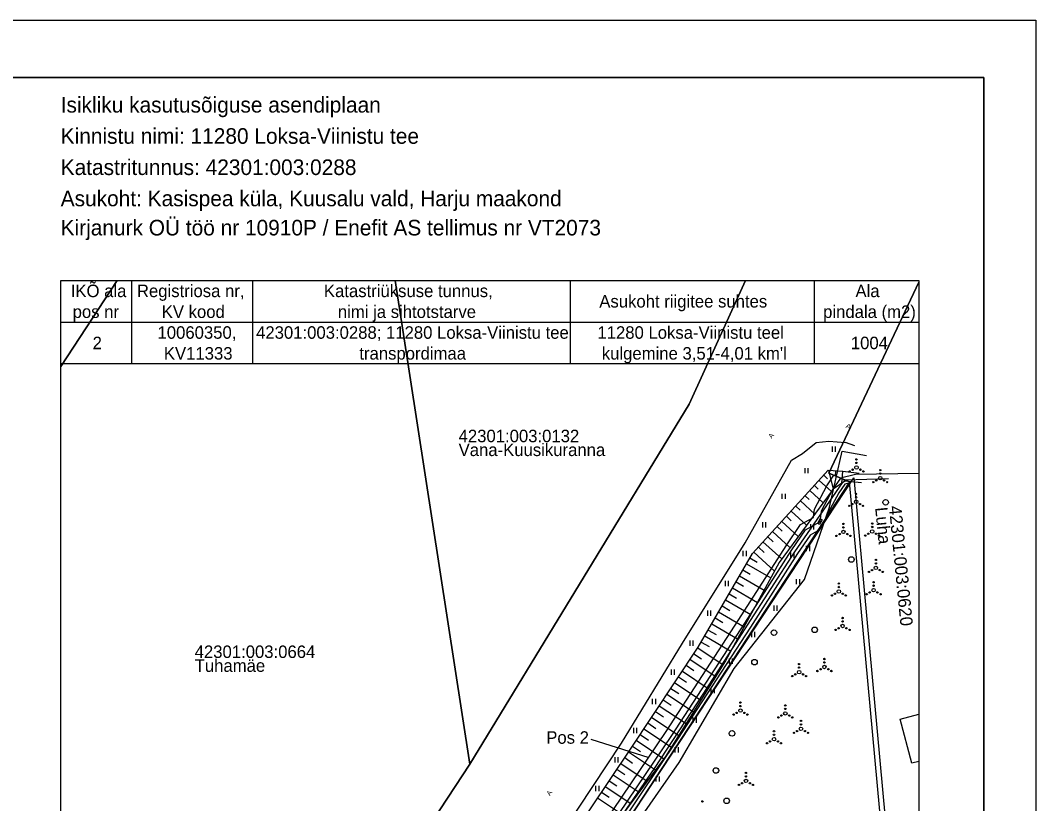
# Model space of a CAD drawing. Extents: x 599446 to 599962, y 6608194 to 6608886.
# Drawn here: x 599815.8 to 599962.3, y 6608773.2 to 6608886.1 of the extents above; entities that cross this region are included whole.
import ezdxf

# ---------------------------------------------------------------- set-up
doc = ezdxf.new("R2010")
doc.units = 0
for name, color, linetype in [('Default', 7, 'Continuous'), ('HALJASTUS', 7, 'Continuous'), ('HOONE', 7, 'Continuous'), ('KASUTUSALA', 7, 'Continuous'), ('MPKAABEL', 7, 'Continuous'), ('PIIR', 7, 'Continuous'), ('PR_SIDE', 7, 'Continuous'), ('proj_trass_kliendiliin kaabel', 7, 'Continuous'), ('RELJEEF', 7, 'Continuous'), ('TEE', 7, 'Continuous'), ('VORMISTUS_3', 7, 'Continuous')]:
    doc.layers.add(name, color=color, linetype=linetype)

msp = doc.modelspace()

# ---------------------------------------------------------------- linework, layer by layer
at = {"layer": 'Default'}
msp.add_lwpolyline([(599930.83, 6608813.56), (599931.21, 6608814.28), (599931.48, 6608814.13), (599931.1, 6608813.42)], close=True, dxfattribs=at)
at = {"layer": 'HALJASTUS'}
for p, q in [((599932.9, 6608824.67), (599932.9, 6608823.91)), ((599933.35, 6608824.67), (599933.35, 6608823.91)), ((599928.97, 6608821.58), (599928.97, 6608820.82)), ((599929.42, 6608821.58), (599929.42, 6608820.82)), ((599925.68, 6608817.88), (599925.68, 6608817.12)), ((599926.14, 6608817.88), (599926.14, 6608817.12)), ((599922.86, 6608813.76), (599922.86, 6608812.99)), ((599923.31, 6608813.76), (599923.31, 6608812.99)), ((599929.78, 6608813.48), (599929.78, 6608812.72)), ((599930.24, 6608813.48), (599930.24, 6608812.72)), ((599920.05, 6608809.62), (599920.05, 6608808.86)), ((599920.5, 6608809.62), (599920.5, 6608808.86)), ((599926.91, 6608809.38), (599926.91, 6608808.62)), ((599927.37, 6608809.38), (599927.37, 6608808.62)), ((599929.19, 6608810.35), (599929.19, 6608809.59)), ((599929.64, 6608810.35), (599929.64, 6608809.59)), ((599917.49, 6608805.33), (599917.49, 6608804.56)), ((599917.94, 6608805.33), (599917.94, 6608804.56)), ((599927.74, 6608805.58), (599927.74, 6608804.82)), ((599928.19, 6608805.58), (599928.19, 6608804.82)), ((599914.93, 6608801.03), (599914.93, 6608800.27)), ((599915.39, 6608801.03), (599915.39, 6608800.27)), ((599924.5, 6608801.77), (599924.5, 6608801.01)), ((599924.96, 6608801.77), (599924.96, 6608801.01)), ((599921.27, 6608797.95), (599921.27, 6608797.19)), ((599921.73, 6608797.95), (599921.73, 6608797.19)), ((599912.38, 6608796.73), (599912.38, 6608795.97)), ((599912.83, 6608796.73), (599912.83, 6608795.97)), ((599918.04, 6608794.14), (599918.04, 6608793.37)), ((599918.5, 6608794.14), (599918.5, 6608793.37)), ((599909.68, 6608792.52), (599909.68, 6608791.76)), ((599910.13, 6608792.52), (599910.13, 6608791.76)), ((599915.43, 6608789.87), (599915.43, 6608789.11)), ((599915.89, 6608789.87), (599915.89, 6608789.11)), ((599906.97, 6608788.32), (599906.97, 6608787.56)), ((599907.43, 6608788.32), (599907.43, 6608787.56)), ((599912.83, 6608785.6), (599912.83, 6608784.84)), ((599913.29, 6608785.6), (599913.29, 6608784.84)), ((599904.27, 6608784.11), (599904.27, 6608783.35)), ((599904.72, 6608784.11), (599904.72, 6608783.35)), ((599901.56, 6608779.91), (599901.56, 6608779.15)), ((599902.02, 6608779.91), (599902.02, 6608779.15)), ((599910.23, 6608781.33), (599910.23, 6608780.57)), ((599910.69, 6608781.33), (599910.69, 6608780.57)), ((599907.5, 6608777.14), (599907.5, 6608776.38)), ((599907.96, 6608777.14), (599907.96, 6608776.38)), ((599898.79, 6608775.75), (599898.79, 6608774.99)), ((599899.24, 6608775.75), (599899.24, 6608774.99))]:
    msp.add_line(p, q, dxfattribs=at)
msp.add_lwpolyline([(599852.54, 6608691.11), (599853.6, 6608692.39), (599867.47, 6608716.75), (599880.24, 6608735.62), (599894.9, 6608756.22), (599910.84, 6608779.13), (599918.77, 6608792.66), (599928.93, 6608805.49), (599932.52, 6608815.94), (599934.35, 6608823.99), (599937.89, 6608823.39)], dxfattribs=at)
for centre, radius in [((599936.42, 6608822.81), 0.1), ((599936.42, 6608822.31), 0.1), ((599935.42, 6608821.09), 0.1), ((599935.86, 6608821.34), 0.1), ((599936.42, 6608821.66), 0.25), ((599936.99, 6608821.34), 0.1), ((599937.42, 6608821.09), 0.1), ((599939.85, 6608821.27), 0.1), ((599938.85, 6608819.54), 0.1), ((599939.28, 6608819.79), 0.1), ((599939.85, 6608820.12), 0.25), ((599939.85, 6608820.77), 0.1), ((599940.41, 6608819.79), 0.1), ((599940.85, 6608819.54), 0.1), ((599936.38, 6608816.71), 0.25), ((599936.38, 6608817.86), 0.1), ((599936.38, 6608817.36), 0.1), ((599940.63, 6608816.63), 0.4), ((599935.38, 6608816.13), 0.1), ((599935.81, 6608816.38), 0.1), ((599936.94, 6608816.38), 0.1), ((599937.38, 6608816.13), 0.1), ((599934.54, 6608813.52), 0.1), ((599938.69, 6608813.58), 0.1), ((599933.98, 6608812.05), 0.1), ((599934.54, 6608812.37), 0.25), ((599934.54, 6608813.02), 0.1), ((599935.11, 6608812.05), 0.1), ((599938.12, 6608812.1), 0.1), ((599938.69, 6608812.43), 0.25), ((599938.69, 6608813.08), 0.1), ((599939.25, 6608812.1), 0.1), ((599933.54, 6608811.8), 0.1), ((599935.54, 6608811.8), 0.1), ((599937.69, 6608811.85), 0.1), ((599939.69, 6608811.85), 0.1), ((599935.69, 6608808.39), 0.4), ((599939.22, 6608808.33), 0.1), ((599939.22, 6608807.83), 0.1), ((599938.22, 6608806.61), 0.1), ((599938.66, 6608806.86), 0.1), ((599939.22, 6608807.18), 0.25), ((599939.79, 6608806.86), 0.1), ((599940.22, 6608806.61), 0.1), ((599933.88, 6608804.93), 0.1), ((599938.89, 6608805.12), 0.1), ((599933.32, 6608803.46), 0.1), ((599933.88, 6608803.78), 0.25), ((599933.88, 6608804.43), 0.1), ((599934.45, 6608803.46), 0.1), ((599937.89, 6608803.39), 0.1), ((599938.32, 6608803.64), 0.1), ((599938.89, 6608803.97), 0.25), ((599938.89, 6608804.62), 0.1), ((599939.45, 6608803.64), 0.1), ((599939.89, 6608803.39), 0.1), ((599932.88, 6608803.21), 0.1), ((599934.88, 6608803.21), 0.1), ((599934.42, 6608798.81), 0.25), ((599934.42, 6608799.96), 0.1), ((599934.42, 6608799.46), 0.1), ((599924.52, 6608797.85), 0.4), ((599930.39, 6608798.25), 0.4), ((599933.42, 6608798.24), 0.1), ((599933.85, 6608798.49), 0.1), ((599934.98, 6608798.49), 0.1), ((599935.42, 6608798.24), 0.1), ((599921.71, 6608793.6), 0.4), ((599928.15, 6608793.31), 0.1), ((599931.8, 6608792.9), 0.25), ((599931.8, 6608794.05), 0.1), ((599931.8, 6608793.55), 0.1), ((599927.15, 6608791.59), 0.1), ((599927.59, 6608791.84), 0.1), ((599928.15, 6608792.16), 0.25), ((599928.15, 6608792.81), 0.1), ((599928.72, 6608791.84), 0.1), ((599929.15, 6608791.59), 0.1), ((599930.8, 6608792.32), 0.1), ((599931.24, 6608792.57), 0.1), ((599932.37, 6608792.57), 0.1), ((599932.8, 6608792.32), 0.1), ((599919.69, 6608787.77), 0.1), ((599919.69, 6608787.27), 0.1), ((599926.16, 6608787.36), 0.1), ((599918.69, 6608786.04), 0.1), ((599919.13, 6608786.29), 0.1), ((599919.69, 6608786.62), 0.25), ((599920.26, 6608786.29), 0.1), ((599920.69, 6608786.04), 0.1), ((599925.59, 6608785.89), 0.1), ((599926.16, 6608786.21), 0.25), ((599926.16, 6608786.86), 0.1), ((599926.72, 6608785.89), 0.1), ((599925.16, 6608785.64), 0.1), ((599927.16, 6608785.64), 0.1), ((599928.42, 6608785.13), 0.1), ((599928.42, 6608784.63), 0.1), ((599918.48, 6608783.33), 0.4), ((599924.53, 6608783.64), 0.1), ((599924.53, 6608783.14), 0.1), ((599927.42, 6608783.41), 0.1), ((599927.86, 6608783.66), 0.1), ((599928.42, 6608783.98), 0.25), ((599928.99, 6608783.66), 0.1), ((599929.42, 6608783.41), 0.1), ((599923.53, 6608781.92), 0.1), ((599923.96, 6608782.17), 0.1), ((599924.53, 6608782.49), 0.25), ((599925.09, 6608782.17), 0.1), ((599925.53, 6608781.92), 0.1), ((599916.15, 6608777.98), 0.4), ((599920.48, 6608777.63), 0.1), ((599920.48, 6608777.13), 0.1), ((599919.48, 6608775.9), 0.1), ((599919.92, 6608776.15), 0.1), ((599920.48, 6608776.48), 0.25), ((599921.05, 6608776.15), 0.1), ((599921.48, 6608775.9), 0.1), ((599914.21, 6608773.52), 0.1), ((599917.69, 6608773.61), 0.4)]:
    msp.add_circle(centre, radius, dxfattribs=at)
at = {"layer": 'HOONE'}
msp.add_lwpolyline([(599945.4, 6608779.28), (599944.41, 6608779.02), (599942.72, 6608785.37), (599945.4, 6608786.08)], dxfattribs=at)
at = {"layer": 'KASUTUSALA'}
msp.add_lwpolyline([(599897.59, 6608766.72), (599908.96, 6608783.58), (599919.46, 6608799.75), (599926.27, 6608810.34), (599928.36, 6608813.42), (599930.22, 6608814.47), (599930.37, 6608815.67), (599932.17, 6608819.03), (599933.17, 6608820.53), (599935.43, 6608819.59), (599935.3, 6608819.39), (599934.73, 6608819.25), (599933.89, 6608818), (599932.31, 6608815.06), (599932.27, 6608814.78), (599930.76, 6608812.48), (599929.75, 6608811.91), (599927.94, 6608809.24), (599921.14, 6608798.66), (599910.63, 6608782.48), (599899.24, 6608765.59)], dxfattribs=at)
at = {"layer": 'MPKAABEL'}
msp.add_lwpolyline([(599850.04, 6608691.11), (599852.92, 6608695.67), (599859.86, 6608706.62), (599864.89, 6608714.39), (599871.03, 6608723.6), (599876.62, 6608731.9), (599883.44, 6608742.77), (599889.53, 6608752.39), (599895.65, 6608761.17), (599900.8, 6608768.87), (599907.3, 6608778.25), (599914.42, 6608789.11), (599920.72, 6608798.93), (599927.52, 6608809.51), (599934.42, 6608819.43), (599934.81, 6608819.9), (599941.02, 6608820.09)], dxfattribs=at)
at = {"layer": 'PIIR'}
for points in [[(599829.8, 6608848.61), (599821.65, 6608836.23)], [(599821.65, 6608836.23), (599829.8, 6608848.61)], [(599869.91, 6608848.61), (599880.68, 6608778.91), (599822.96, 6608691.11)], [(599822.96, 6608691.11), (599880.68, 6608778.91), (599912.29, 6608830.77), (599920.4, 6608848.61)], [(599945.4, 6608848.37), (599932.44, 6608820.83), (599935.43, 6608819.59), (599886.06, 6608744.32), (599851.22, 6608691.11)], [(599920.4, 6608848.61), (599912.29, 6608830.77), (599880.68, 6608778.91), (599869.91, 6608848.61)], [(599945.4, 6608711.12), (599935.43, 6608819.59), (599932.44, 6608820.83), (599945.4, 6608848.39)], [(599894.31, 6608691.11), (599886.06, 6608744.32), (599936.05, 6608820.15), (599945.4, 6608718.31)]]:
    msp.add_lwpolyline(points, dxfattribs=at)
at = {"layer": 'PR_SIDE'}
msp.add_lwpolyline([(599780.53, 6608585.3), (599792.21, 6608602.29), (599793.2, 6608606.88), (599806.34, 6608627.01), (599816.97, 6608642.78), (599827.08, 6608657.37), (599832.75, 6608665.24), (599837.96, 6608672.78), (599843.96, 6608682.55), (599849.32, 6608690.88), (599859.61, 6608707.16), (599866.76, 6608718.14), (599874.33, 6608729.39), (599883.02, 6608743.03), (599889.12, 6608752.66), (599898.41, 6608766.16), (599909.8, 6608783.03), (599920.3, 6608799.2), (599927.11, 6608809.79), (599929.06, 6608812.66), (599931.15, 6608813.84)], dxfattribs=at)
at = {"layer": 'proj_trass_kliendiliin kaabel'}
msp.add_lwpolyline([(599945.4, 6608820.77), (599936.29, 6608820.65), (599934.12, 6608820.14), (599933.03, 6608818.51), (599931.34, 6608815.37), (599931.15, 6608813.84)], dxfattribs=at)
at = {"layer": 'RELJEEF'}
for p, q in [((599932.39, 6608821.25), (599933.04, 6608818.51)), ((599933.39, 6608821.18), (599933.34, 6608820.42)), ((599934.39, 6608821.12), (599934.28, 6608819.35)), ((599931.03, 6608819.8), (599932.8, 6608818.18)), ((599931.71, 6608820.53), (599932.26, 6608820.03)), ((599929.68, 6608818.32), (599931.61, 6608816.56)), ((599930.36, 6608819.06), (599930.91, 6608818.55)), ((599928.34, 6608816.84), (599930.41, 6608814.94)), ((599929.01, 6608817.58), (599929.61, 6608817.03)), ((599926.99, 6608815.36), (599929.22, 6608813.33)), ((599927.66, 6608816.1), (599928.31, 6608815.51)), ((599925.64, 6608813.89), (599928.03, 6608811.71)), ((599926.31, 6608814.62), (599927.01, 6608813.99)), ((599924.29, 6608812.41), (599926.84, 6608810.09)), ((599924.97, 6608813.15), (599925.71, 6608812.47)), ((599922.94, 6608810.93), (599925.65, 6608808.47)), ((599923.62, 6608811.67), (599924.41, 6608810.95)), ((599921.6, 6608809.45), (599924.6, 6608806.71)), ((599922.27, 6608810.19), (599923.12, 6608809.42)), ((599920.55, 6608807.76), (599924.06, 6608805.73)), ((599921.05, 6608808.62), (599922.1, 6608808.02)), ((599920.05, 6608806.89), (599921.11, 6608806.28)), ((599919.05, 6608805.16), (599920.12, 6608804.54)), ((599919.55, 6608806.03), (599923.1, 6608803.97)), ((599918.05, 6608803.43), (599919.13, 6608802.8)), ((599918.55, 6608804.29), (599922.14, 6608802.21)), ((599917.54, 6608802.56), (599921.19, 6608800.46)), ((599916.54, 6608800.83), (599920.23, 6608798.7)), ((599917.04, 6608801.7), (599918.14, 6608801.06)), ((599915.54, 6608799.1), (599919.27, 6608796.94)), ((599916.04, 6608799.97), (599917.15, 6608799.32)), ((599915.04, 6608798.23), (599916.17, 6608797.58)), ((599914.04, 6608796.5), (599915.18, 6608795.85)), ((599914.54, 6608797.37), (599918.31, 6608795.19)), ((599912.98, 6608794.81), (599914.08, 6608794.07)), ((599913.53, 6608795.64), (599917.18, 6608793.21)), ((599911.87, 6608793.15), (599912.98, 6608792.4)), ((599912.42, 6608793.98), (599916.12, 6608791.51)), ((599911.31, 6608792.31), (599915.05, 6608789.82)), ((599910.2, 6608790.65), (599913.99, 6608788.12)), ((599910.76, 6608791.48), (599911.89, 6608790.73)), ((599909.09, 6608788.99), (599912.93, 6608786.43)), ((599909.65, 6608789.82), (599910.79, 6608789.06)), ((599907.98, 6608787.32), (599911.86, 6608784.74)), ((599908.54, 6608788.15), (599909.69, 6608787.38)), ((599907.43, 6608786.49), (599908.6, 6608785.71)), ((599906.32, 6608784.83), (599907.5, 6608784.04)), ((599906.87, 6608785.66), (599910.8, 6608783.04)), ((599905.21, 6608783.16), (599906.41, 6608782.36)), ((599905.76, 6608784), (599909.73, 6608781.35)), ((599904.1, 6608781.5), (599905.28, 6608780.71)), ((599904.65, 6608782.33), (599908.64, 6608779.67)), ((599903.54, 6608780.67), (599907.44, 6608778.06)), ((599902.43, 6608779.01), (599906.25, 6608776.45)), ((599902.99, 6608779.84), (599904.14, 6608779.06)), ((599901.32, 6608777.34), (599905.06, 6608774.84)), ((599901.87, 6608778.18), (599903.01, 6608777.42)), ((599900.2, 6608775.68), (599903.87, 6608773.23)), ((599900.76, 6608776.51), (599901.87, 6608775.77)), ((599899.65, 6608774.85), (599900.73, 6608774.12)), ((599899.09, 6608774.02), (599902.67, 6608771.62))]:
    msp.add_line(p, q, dxfattribs=at)
for points in [[(599846.39, 6608691.11), (599851.45, 6608698.53), (599862.06, 6608718.57), (599875.76, 6608738.59), (599889.36, 6608759.49), (599903.81, 6608781.08), (599913.6, 6608795.74), (599921.41, 6608809.25), (599932.36, 6608821.25), (599934.46, 6608821.12), (599936.81, 6608820.86)], [(599937.14, 6608819.45), (599934.76, 6608819.68), (599933.04, 6608818.51), (599925.29, 6608807.98), (599917.54, 6608793.77), (599908.88, 6608779.99), (599892.34, 6608757.7), (599878.25, 6608736.87), (599866.36, 6608717.34), (599851.99, 6608693.55), (599850.12, 6608691.11)]]:
    msp.add_lwpolyline(points, dxfattribs=at)
at = {"layer": 'TEE'}
msp.add_line((599936.19, 6608824.76), (599934.85, 6608825.27), dxfattribs=at)
msp.add_lwpolyline([(599841.84, 6608691.11), (599848.1, 6608700.54), (599860.76, 6608719.12), (599874.14, 6608739.21), (599888.04, 6608760.08), (599902.52, 6608781.93), (599911.34, 6608796.32), (599920.35, 6608810.81), (599927.04, 6608822.73), (599928.64, 6608823.67), (599930.63, 6608825.26), (599932.44, 6608825.46), (599934.85, 6608825.27)], dxfattribs=at)
at = {"layer": 'VORMISTUS_3'}
for p, q in [((599831.85, 6608848.61), (599831.85, 6608836.61)), ((599849.32, 6608848.61), (599849.32, 6608836.61)), ((599895.15, 6608848.61), (599895.15, 6608836.61)), ((599930.32, 6608848.61), (599930.32, 6608836.61)), ((599821.65, 6608842.61), (599945.4, 6608842.61)), ((599906.52, 6608779.83), (599898.17, 6608782.43))]:
    msp.add_line(p, q, dxfattribs=at)
for points in [[(599804.77, 6608886.11), (599962.27, 6608886.11), (599962.27, 6608663.36), (599804.77, 6608663.36)], [(599812.27, 6608671.61), (599954.77, 6608671.61), (599954.77, 6608877.86), (599812.27, 6608877.86)], [(599812.27, 6608877.86), (599954.77, 6608877.86), (599954.77, 6608671.61), (599812.27, 6608671.61)], [(599945.4, 6608691.11), (599821.65, 6608691.11), (599821.65, 6608848.61), (599945.4, 6608848.61)], [(599821.65, 6608848.61), (599945.4, 6608848.61), (599945.4, 6608836.61), (599821.65, 6608836.61)]]:
    msp.add_lwpolyline(points, close=True, dxfattribs=at)

# ---------------------------------------------------------------- texts
at = {"layer": 'PIIR'}
for s, p in [('42301:003:0132', (599879.04, 6608825.3)), ('Vana-Kuusikuranna', (599879.04, 6608823.3)), ('42301:003:0664', (599840.97, 6608794.2)), ('Tuhamäe', (599840.97, 6608792.2))]:
    msp.add_text(s, height=1.8, dxfattribs=at).set_placement(p)
for s, p in [('Luha', (599939.11, 6608815.86)), ('42301:003:0620', (599941.1, 6608816.05))]:
    msp.add_text(s, height=1.8, rotation=275.549, dxfattribs=at).set_placement(p)
at = {"layer": 'TEE'}
for rotation, p in [(337.5396, (599934.81, 6608827.39)), (55.0319, (599924.21, 6608825.77)), (55.8113, (599892.22, 6608774.27))]:
    msp.add_text('A', height=0.7, rotation=rotation, dxfattribs=at).set_placement(p)
at = {"layer": 'VORMISTUS_3'}
for s, height, p in [('Isikliku kasutusõiguse asendiplaan', 2.25, (599821.65, 6608872.81)), ('Kinnistu nimi: 11280 Loksa-Viinistu tee', 2.25, (599821.65, 6608868.31)), ('Katastritunnus: 42301:003:0288', 2.25, (599821.65, 6608863.81)), ('Asukoht: Kasispea küla, Kuusalu vald, Harju maakond', 2.25, (599821.65, 6608859.31)), ('IKÕ ala', 1.8, (599823.1, 6608846.21)), ('Registriosa nr,', 1.8, (599832.64, 6608846.21)), ('Katastriüksuse tunnus,', 1.8, (599859.61, 6608846.21)), ('Ala', 1.8, (599936.28, 6608846.21)), ('Asukoht riigitee suhtes ', 1.8, (599899.33, 6608844.71)), ('pos nr', 1.8, (599823.37, 6608843.21)), ('KV kood', 1.8, (599836.22, 6608843.21)), ('nimi ja sihtotstarve', 1.8, (599861.62, 6608843.21)), ('pindala (m2)', 1.8, (599931.61, 6608843.21)), ('10060350,', 1.8, (599835.61, 6608840.21)), ('42301:003:0288; 11280 Loksa-Viinistu tee', 1.8, (599849.83, 6608840.21)), ('11280 Loksa-Viinistu teel', 1.8, (599899.06, 6608840.21)), ('2', 1.8, (599826.25, 6608838.71)), ('1004', 1.8, (599935.61, 6608838.71)), ('KV11333', 1.8, (599836.53, 6608837.21)), ('transpordimaa', 1.8, (599864.72, 6608837.21)), ("kulgemine 3,51-4,01 km'l", 1.8, (599899.69, 6608837.21)), ('Pos 2', 1.8, (599891.68, 6608781.84))]:
    msp.add_text(s, height=height, dxfattribs=at).set_placement(p)
msp.add_text('Kirjanurk OÜ töö nr 10910P / Enefit AS tellimus nr VT2073', height=2.25, rotation=360, dxfattribs=at).set_placement((599821.64, 6608855.1))

doc.saveas('drawing.dxf')
